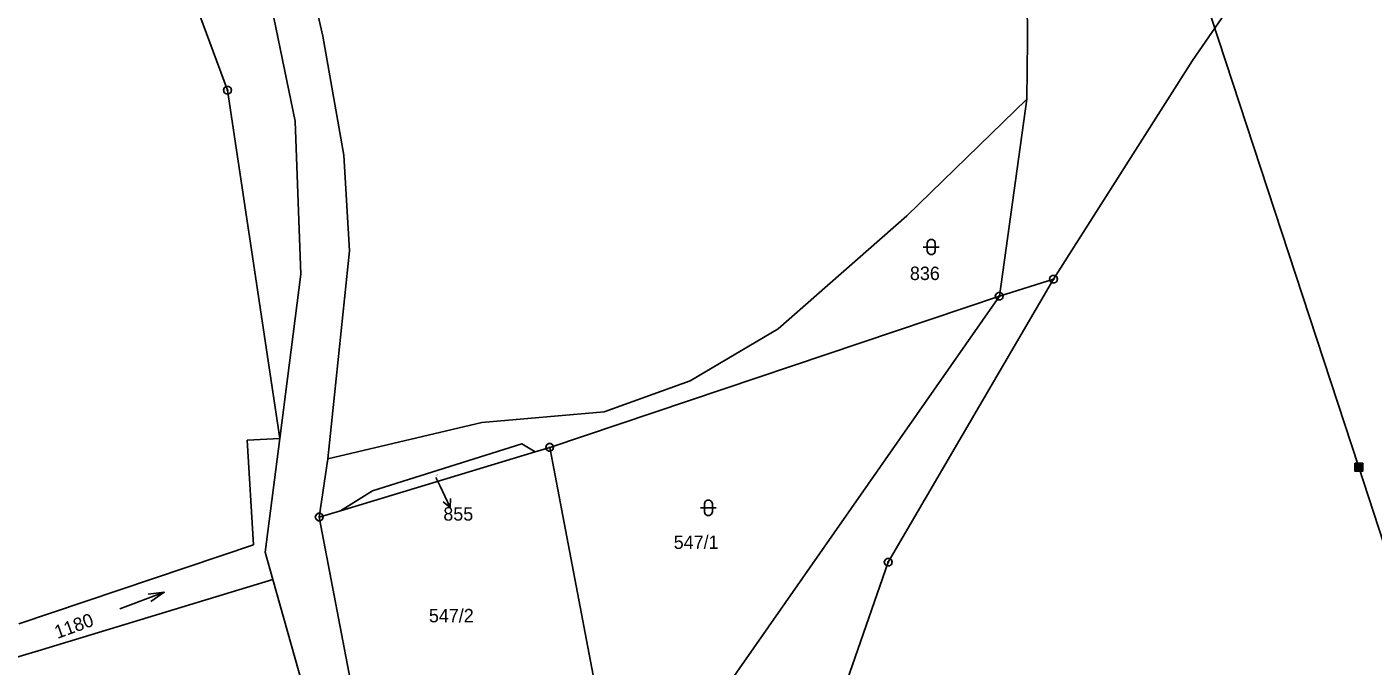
# Model space of a CAD drawing. Extents: x -812394 to -807601, y -1013098 to -1009266.
# Drawn here: x -809003.5 to -808832.6, y -1011568.5 to -1011487.4 of the extents above; entities that cross this region are included whole.
import ezdxf

# ---------------------------------------------------------------- set-up
doc = ezdxf.new("R2010")
doc.units = 0
for name, color, linetype in [('KN_HRANICE', 7, 'Continuous'), ('KN_KULTURY', 7, 'Continuous'), ('KN_MEZNIKY', 7, 'Continuous'), ('KN_PARCELY', 7, 'Continuous'), ('KN_VEDENI', 7, 'Continuous')]:
    doc.layers.add(name, color=color, linetype=linetype)

# ---------------------------------------------------------------- blocks, each defined once
blk = doc.blocks.new('316')
for points in [[(-0.5, 1.5), (-0.4, 1.79), (-0.15, 1.97), (0.16, 1.97), (0.41, 1.79), (0.51, 1.5), (0.51, 0.5), (0.41, 0.21), (0.16, 0.03), (-0.15, 0.03), (-0.4, 0.21), (-0.5, 0.5), (-0.5, 1.5)], [(-1, 1), (0.27, 1), (1, 1)]]:
    blk.add_lwpolyline(points)
blk = doc.blocks.new('802')
blk.add_line((-3, 0), (3, 0))
blk.add_lwpolyline([(1, 0.5), (3, 0), (1, -0.5)])
blk = doc.blocks.new('10292')
blk.add_line((0, 3), (0, 0))
blk.add_lwpolyline([(-0.5, 2), (0, 3), (0.5, 2)])
blk = doc.blocks.new('105')
blk.add_line((-0.12, 0), (0.12, 0))
blk.add_lwpolyline([(0.15, 0.48), (0.4, 0.3), (0.5, 0.01), (0.4, -0.28), (0.15, -0.46), (-0.16, -0.46), (-0.41, -0.28), (-0.51, 0.01), (-0.41, 0.3), (-0.16, 0.48), (0.15, 0.48)])
blk = doc.blocks.new('602')
blk.add_lwpolyline([(-0.5, 0.5), (0.5, 0.5), (0.5, -0.5), (-0.5, -0.5), (-0.5, 0.5), (-0.44, 0.44), (0.44, 0.44), (0.44, 0.36), (-0.44, 0.36), (-0.44, 0.28), (0.44, 0.28), (0.44, 0.2), (-0.44, 0.2), (-0.44, 0.12), (0.44, 0.12), (0.44, 0.04), (-0.44, 0.04), (-0.44, -0.04), (0.44, -0.04), (0.44, -0.12), (-0.44, -0.12), (-0.44, -0.2), (0.44, -0.2), (0.44, -0.28), (-0.44, -0.28), (-0.44, -0.36), (0.44, -0.36), (0.44, -0.44), (-0.44, -0.44)])

msp = doc.modelspace()

# ---------------------------------------------------------------- linework, layer by layer
at = {"layer": 'KN_HRANICE'}
for p, q in [((-808965.96, -1011488.59), (-808970.28, -1011469.05)), ((-808974.44, -1011475.12), (-808969.45, -1011499.37)), ((-808963.26, -1011503.69), (-808965.96, -1011488.59)), ((-808873.2, -1011519.41), (-808855.58, -1011491.65)), ((-808971.42, -1011539.63), (-808978.04, -1011495.45)), ((-808891.84, -1011511.36), (-808876.58, -1011496.57)), ((-808876.58, -1011496.57), (-808880.08, -1011521.57)), ((-808969.45, -1011499.37), (-808968.75, -1011518.78)), ((-808962.56, -1011515.81), (-808963.26, -1011503.69)), ((-808908.15, -1011525.71), (-808891.84, -1011511.36)), ((-808965.32, -1011542.2), (-808962.56, -1011515.81)), ((-808968.75, -1011518.78), (-808971.42, -1011539.63)), ((-808894.18, -1011555.33), (-808873.2, -1011519.41)), ((-808873.2, -1011519.41), (-808880.08, -1011521.57)), ((-808880.08, -1011521.57), (-808937.15, -1011540.75)), ((-808915.66, -1011572.49), (-808880.08, -1011521.57)), ((-808919.33, -1011532.32), (-808908.15, -1011525.71)), ((-808930.24, -1011536.22), (-808919.33, -1011532.32)), ((-808945.75, -1011537.6), (-808930.24, -1011536.22)), ((-808965.32, -1011542.2), (-808945.75, -1011537.6)), ((-808975.53, -1011539.84), (-808971.42, -1011539.63)), ((-808974.75, -1011553.11), (-808975.53, -1011539.84)), ((-808971.42, -1011539.63), (-808973.26, -1011554.04)), ((-808939.01, -1011541.31), (-808963.72, -1011548.78)), ((-808937.15, -1011540.75), (-808939.01, -1011541.31)), ((-808937.15, -1011540.75), (-808931.47, -1011570.52)), ((-808966.39, -1011549.59), (-808965.32, -1011542.2)), ((-808963.72, -1011548.78), (-808966.39, -1011549.59)), ((-808966.39, -1011549.59), (-808960.16, -1011582.4)), ((-809004.54, -1011563.13), (-808974.75, -1011553.11)), ((-808973.26, -1011554.04), (-808972.29, -1011557.49)), ((-808899.78, -1011571.39), (-808894.18, -1011555.33)), ((-809001.64, -1011566.41), (-808972.29, -1011557.49)), ((-808972.29, -1011557.49), (-808961.13, -1011597.23)), ((-809019.32, -1011571.78), (-809001.64, -1011566.41))]:
    msp.add_line(p, q, dxfattribs=at)
for points in [[(-808876.58, -1011496.57), (-808876.5, -1011489.14), (-808876.71, -1011462.42), (-808881.55, -1011440.6), (-808894.69, -1011432.01), (-808924.68, -1011432.91), (-808919.61, -1011417.84), (-808910.04, -1011399.6), (-808897.42, -1011390.94), (-808865.7, -1011380.51), (-808873.42, -1011358.96)], [(-809039.69, -1011388.93), (-809024.1, -1011392.16), (-809015.94, -1011401.01), (-809005.51, -1011425.71), (-808989.67, -1011464.02), (-808978.04, -1011495.45)], [(-808777.29, -1011424.22), (-808793.61, -1011431.29), (-808814.66, -1011442.69), (-808827.8, -1011455.19), (-808842.35, -1011472.52), (-808855.58, -1011491.65)], [(-808963.72, -1011548.78), (-808959.65, -1011546.28), (-808940.7, -1011540.29), (-808939.01, -1011541.31)]]:
    msp.add_lwpolyline(points, dxfattribs=at)
at = {"layer": 'KN_PARCELY'}
msp.add_line((-808951.59, -1011544.55), (-808951.07, -1011545.65), dxfattribs=at)
at = {"layer": 'KN_VEDENI'}
msp.add_lwpolyline([(-809513.17, -1009474.26), (-809487.03, -1009553.9), (-809382.67, -1009871.8), (-809271.71, -1010210.69), (-809133.29, -1010632.77), (-809030.14, -1010947.95), (-808933.39, -1011241.46), (-808834.45, -1011543.27), (-808752.75, -1011794.76), (-808648.03, -1012113.89), (-808628.65, -1012173.95)], dxfattribs=at)

# ---------------------------------------------------------------- block references
at = {"layer": 'KN_KULTURY'}
for p in [(-808888.73, -1011516.33), (-808917.01, -1011549.41)]:
    msp.add_blockref('316', p, dxfattribs=at)
at = {"layer": 'KN_KULTURY', "rotation": 20.511889}
msp.add_blockref('802', (-808988.88, -1011560.18), dxfattribs=at)
at = {"layer": 'KN_MEZNIKY'}
for p in [(-808978.04, -1011495.45), (-808873.2, -1011519.41), (-808880.08, -1011521.57), (-808937.15, -1011540.75), (-808966.39, -1011549.59), (-808894.18, -1011555.33)]:
    msp.add_blockref('105', p, dxfattribs=at)
at = {"layer": 'KN_PARCELY', "rotation": -154.30815200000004}
msp.add_blockref('10292', (-808951.07, -1011545.65), dxfattribs=at)
at = {"layer": 'KN_VEDENI'}
msp.add_blockref('602', (-808834.45, -1011543.27), dxfattribs=at)

# ---------------------------------------------------------------- texts
at = {"layer": 'KN_PARCELY'}
for s, p in [('836', (-808891.43, -1011519.52)), ('855', (-808950.65, -1011550.04)), ('547/1', (-808921.41, -1011553.63)), ('547/2', (-808952.48, -1011562.94))]:
    msp.add_text(s, height=1.7, dxfattribs=at).set_placement(p)
for s, height, rotation, p in [('855', 0.1, 70.13, (-808951.45, -1011544.4)), ('1180', 1.7, 20.054, (-808999.63, -1011565.06))]:
    msp.add_text(s, height=height, rotation=rotation, dxfattribs=at).set_placement(p)

doc.saveas('drawing.dxf')
